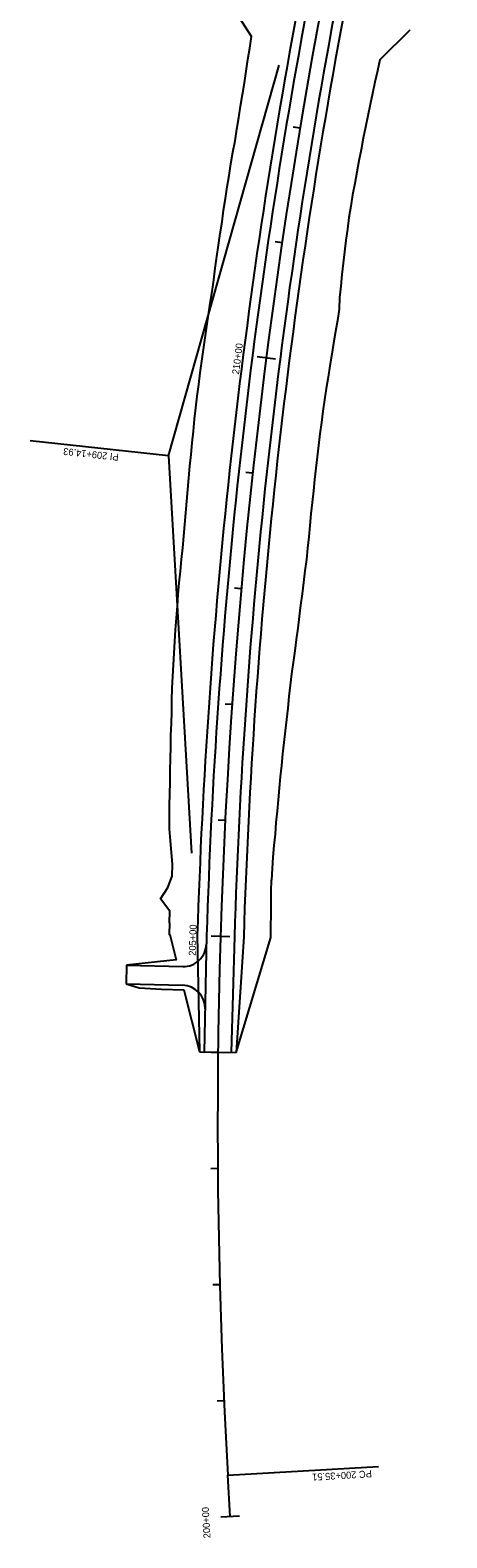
# Model space of a CAD drawing. Extents: x 1441466 to 1476381, y 2042742 to 2057194.
# Drawn here: x 1445527 to 1445886, y 2052949 to 2054247 of the extents above; entities that cross this region are included whole.
import ezdxf

# ---------------------------------------------------------------- set-up
doc = ezdxf.new("R2010")
doc.units = 0
for name, color, linetype in [('R_Horz Alg', 7, 'Continuous'), ('R_Horz Alg Annot', 7, 'Continuous'), ('R_Horz Alg Stationing', 7, 'Continuous'), ('R_Proposed Const Limits', 7, 'Continuous'), ('R_Proposed Road', 7, 'Continuous'), ('S_DRIVEWAY', 7, 'Continuous')]:
    doc.layers.add(name, color=color, linetype=linetype)

msp = doc.modelspace()

# ---------------------------------------------------------------- linework, layer by layer
at = {"layer": 'R_Horz Alg'}
msp.add_line((1445699.3, 2052967.2), (1445697.2, 2053002.6), dxfattribs=at)
msp.add_arc((1450897.1, 2053305.5), 5208.7, 164.1667, 183.3333, dxfattribs=at)
at = {"layer": 'R_Horz Alg Annot'}
for q in [(1445741.5, 2054217), (1445666, 2053538.3)]:
    msp.add_line((1445646.1, 2053880.6), q, dxfattribs=at)
for points in [[(1445646.1, 2053880.6), (1445526.8, 2053893.6)], [(1445697.2, 2053002.6), (1445827, 2053010.2)]]:
    msp.add_lwpolyline(points, dxfattribs=at)
at = {"layer": 'R_Horz Alg Stationing'}
for points in [[(1445753.6, 2054164), (1445759.5, 2054163)], [(1445738, 2054065.1), (1445744, 2054064.3)], [(1445722.4, 2053966.2), (1445738.3, 2053964.2)], [(1445712.7, 2053866.5), (1445718.6, 2053865.9)], [(1445702.9, 2053766.9), (1445708.8, 2053766.4)], [(1445695, 2053667.1), (1445700.9, 2053666.7)], [(1445689, 2053567.2), (1445695, 2053566.9)], [(1445682.9, 2053467.2), (1445698.9, 2053466.7)], [(1445682.8, 2053367), (1445688.8, 2053367)], [(1445682.5, 2053266.9), (1445688.5, 2053267)], [(1445684.2, 2053166.8), (1445690.2, 2053167)], [(1445687.9, 2053066.8), (1445693.9, 2053067)], [(1445691.3, 2052966.7), (1445707.3, 2052967.7)]]:
    msp.add_lwpolyline(points, dxfattribs=at)
at = {"layer": 'R_Proposed Const Limits'}
for points in [[(1445649.1, 2053518.7), (1445649.4, 2053528.8), (1445648.7, 2053538.9), (1445647.9, 2053549), (1445646.9, 2053559.2), (1445646.8, 2053569.3), (1445646.9, 2053579.4), (1445647.2, 2053589.5), (1445647.4, 2053599.6), (1445647.5, 2053609.7), (1445647.8, 2053619.8), (1445648.1, 2053629.9), (1445648.2, 2053640), (1445648.6, 2053650.1), (1445648.9, 2053660.2), (1445649, 2053670.3), (1445649.2, 2053680.4), (1445649.7, 2053690.5), (1445650.3, 2053700.6), (1445650.9, 2053710.7), (1445651.6, 2053720.7), (1445652.2, 2053730.8), (1445653, 2053740.9), (1445653.7, 2053751), (1445654.5, 2053761), (1445655.3, 2053771.1), (1445656.4, 2053781.2), (1445657.4, 2053791.2), (1445658.5, 2053801.3), (1445659.3, 2053811.3), (1445660.2, 2053821.4), (1445661, 2053831.5), (1445661.9, 2053841.5), (1445662.7, 2053851.6), (1445663.6, 2053861.7), (1445664.6, 2053871.7), (1445665.5, 2053881.8), (1445666.5, 2053891.8), (1445667.5, 2053901.9), (1445668.5, 2053912), (1445669.7, 2053922), (1445670.7, 2053932), (1445672.1, 2053942.1), (1445673.4, 2053952.1), (1445674.7, 2053962.1), (1445676.2, 2053972.1), (1445677.6, 2053982.1), (1445679.1, 2053992.1), (1445680.5, 2054002.1), (1445682.1, 2054012.1), (1445683.6, 2054022.1), (1445685.1, 2054032.1), (1445686.3, 2054042.1), (1445687.7, 2054052.1), (1445689.2, 2054062.1), (1445690.6, 2054072.1), (1445692.2, 2054082.1), (1445693.5, 2054092.1), (1445695.1, 2054102.1), (1445696.5, 2054112.1), (1445698.4, 2054122), (1445699.9, 2054132), (1445701.4, 2054142), (1445703.4, 2054151.9), (1445704.9, 2054161.9), (1445706.7, 2054171.9), (1445708.2, 2054181.8), (1445709.8, 2054191.8), (1445711.5, 2054201.8), (1445712.9, 2054211.8), (1445714.5, 2054221.8), (1445716.1, 2054231.7), (1445717.7, 2054241.7), (1445695.1, 2054276.8)], [(1445854.2, 2054247.1), (1445828.3, 2054221.7), (1445826.1, 2054212.1), (1445824, 2054202.4), (1445821.8, 2054192.7), (1445819.8, 2054183.1), (1445817.9, 2054173.4), (1445815.8, 2054163.7), (1445813.9, 2054154), (1445812.1, 2054144.2), (1445810.2, 2054134.5), (1445808.4, 2054124.8), (1445806.7, 2054115), (1445804.8, 2054105.3), (1445803.2, 2054095.5), (1445801.5, 2054085.8), (1445800.4, 2054075.9), (1445798.8, 2054066.2), (1445797.8, 2054056.3), (1445796.5, 2054046.5), (1445795.6, 2054036.6), (1445794.6, 2054026.8), (1445793.6, 2054016.9), (1445793.3, 2054007), (1445791.8, 2053997.2), (1445790.1, 2053987.5), (1445788.4, 2053977.7), (1445786.8, 2053968), (1445785.2, 2053958.2), (1445783.6, 2053948.4), (1445782.1, 2053938.6), (1445780.6, 2053928.8), (1445779.1, 2053919.1), (1445777.9, 2053909.2), (1445776.6, 2053899.4), (1445775.4, 2053889.6), (1445774.3, 2053879.8), (1445773.1, 2053869.9), (1445772, 2053860.1), (1445771, 2053850.3), (1445769.9, 2053840.4), (1445768.9, 2053830.6), (1445767.9, 2053820.7), (1445766.9, 2053810.9), (1445766, 2053801), (1445765.1, 2053791.2), (1445763.7, 2053781.4), (1445762.4, 2053771.5), (1445761.2, 2053761.7), (1445759.9, 2053751.9), (1445758.7, 2053742.1), (1445757.5, 2053732.2), (1445756.2, 2053722.4), (1445754.9, 2053712.6), (1445753.5, 2053702.7), (1445752.2, 2053692.9), (1445751, 2053683.1), (1445749.8, 2053673.2), (1445748.8, 2053663.3), (1445747.7, 2053653.5), (1445746.6, 2053643.6), (1445745.5, 2053633.8), (1445744.4, 2053623.9), (1445743.4, 2053614), (1445742.4, 2053604.2), (1445741.4, 2053594.3), (1445740.5, 2053584.4), (1445739.6, 2053574.5), (1445738.7, 2053564.7), (1445737.9, 2053554.8), (1445737, 2053544.9), (1445736.1, 2053535), (1445735.3, 2053525.1), (1445734.8, 2053515.2)], [(1445646.8, 2053478.4), (1445647.2, 2053488.5), (1445639.2, 2053498.9), (1445645.6, 2053508.7), (1445649.1, 2053518.7)], [(1445704.4, 2053366.8), (1445734.3, 2053465.6), (1445734.3, 2053465.6), (1445734.4, 2053475.5), (1445734.5, 2053485.4), (1445734.5, 2053495.4), (1445734.7, 2053505.3), (1445734.8, 2053515.2)], [(1445646.8, 2053478.4), (1445646.6, 2053468.3), (1445647.1, 2053468.3), (1445652.7, 2053446.4), (1445610, 2053441.9)], [(1445609.6, 2053425.9), (1445620.9, 2053422.5), (1445640, 2053421.3), (1445659.2, 2053420.8), (1445672.7, 2053367.2)]]:
    msp.add_lwpolyline(points, dxfattribs=at)
at = {"layer": 'R_Proposed Road'}
for p, q in [((1445670.9, 2053467.6), (1445672.7, 2053367.2)), ((1445678.9, 2053467.3), (1445676.8, 2053367.1)), ((1445702.9, 2053466.6), (1445700.1, 2053366.8)), ((1445710.9, 2053466.3), (1445704.4, 2053366.8)), ((1445672.7, 2053367.2), (1445704.4, 2053366.8))]:
    msp.add_line(p, q, dxfattribs=at)
for radius in [5228.7, 5220.7, 5196.7, 5188.7]:
    msp.add_arc((1450897.1, 2053305.5), radius, 169.4239, 178.2239, dxfattribs=at)
at = {"layer": 'S_DRIVEWAY'}
for p, q in [((1445610, 2053441.9), (1445609.6, 2053425.9)), ((1445610, 2053441.9), (1445658.3, 2053440.7)), ((1445609.6, 2053425.9), (1445658.1, 2053424.7))]:
    msp.add_line(p, q, dxfattribs=at)
for centre, start, end in [((1445658.8, 2053460.7), 268.6089, 358.8174), ((1445657.6, 2053404.7), 358.8174, 88.6089)]:
    msp.add_arc(centre, 20, start, end, dxfattribs=at)

# ---------------------------------------------------------------- texts
at = {"layer": 'R_Horz Alg Annot'}
for s, rotation, p in [('PI 209+14.93', 173.75, (1445603.4, 2053882.2)), ('PC 200+35.51', 183.3333, (1445821.2, 2053006.9))]:
    msp.add_text(s, height=6, rotation=rotation, dxfattribs=at).set_placement(p)
at = {"layer": 'R_Horz Alg Stationing'}
for s, rotation, p in [('210+00', 82.7239, (1445706.8, 2053950.4)), ('205+00', 88.2239, (1445669.5, 2053449.9)), ('200+00', 93.3333, (1445682.3, 2052948.5))]:
    msp.add_text(s, height=6, rotation=rotation, dxfattribs=at).set_placement(p)

doc.saveas('drawing.dxf')
